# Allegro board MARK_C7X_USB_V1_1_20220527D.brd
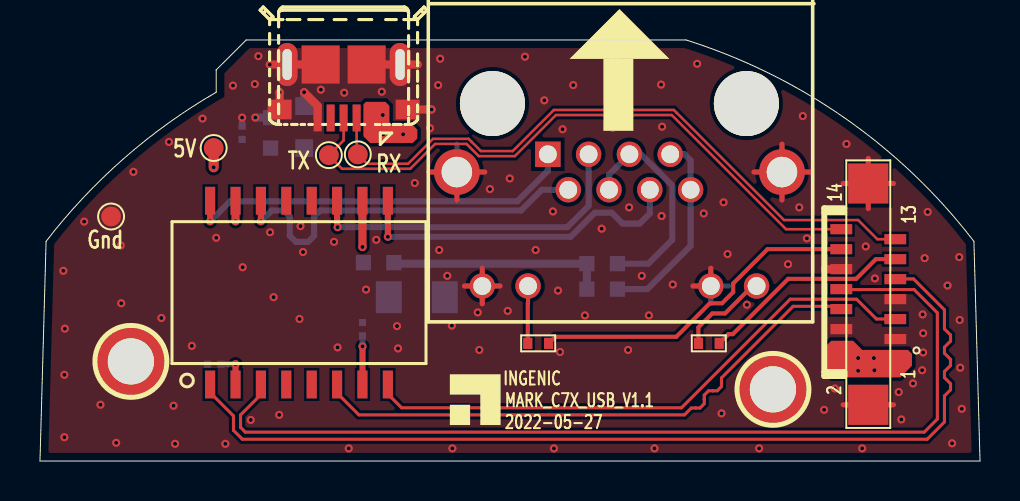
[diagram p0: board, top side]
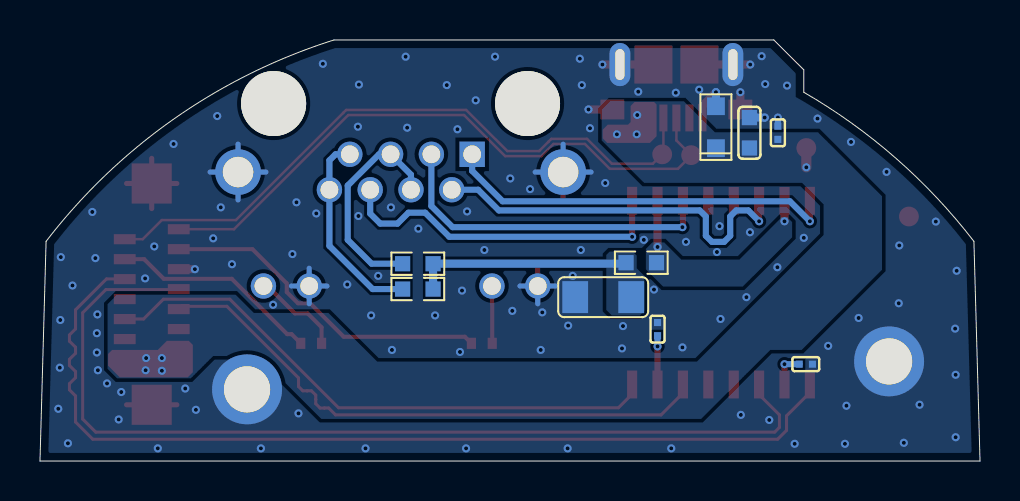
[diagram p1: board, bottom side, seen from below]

Outline 47.02 x 21.08 mm; copper layers: TOP, BOTTOM. Coordinates in mm from the lower left corner of the outline.
Outline path: circle c4.55,4.99 r1.09 ; circle c36.66,3.59 r1.11 ; 0,0 0.3,11 arc(4.19,15.15) 8.81,18.47 8.81,19.58 10.31,21.08 32.31,21.08 arc(40.29,17.15) 46.71,11 47.02,0 0,0

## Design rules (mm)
net group PHY_RX: nets RXN RXP
net group PHY_TX: nets TXN TXP
net group RX: nets RX+ RX-
net group TX: nets TX+ TX-

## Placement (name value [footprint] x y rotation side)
C88  100nF-0201  [C0201]  16.13 6.6 90 bottom
C90  100nF-0201  [C0201]  8.71 4.85 180 bottom
C91  1nF/2KV-1206  [C1206]  18.85 8.2 180 bottom
C162  22uF-0603  [C0603]  11.53 16.43 90 bottom
C163  100nF-0201  [C0201]  10.11 16.43 90 bottom
D14  BZT52C5V1S  [SOD323]  13.21 16.71 270 bottom
HOLE1  T POINT R  [H3D5MM_2D2MM]  4.55 4.99 0 top
HOLE2  T POINT R  [H3D5MM_2D2MM]  36.66 3.59 0 top
J16  MICRO USB  [MICROUSB_B_USB0565]  15.19 17.18 270 top
J20  CON14 0.5mm LT  [FPC-CON14-0D5-LT]  41.43 8.36 90 top
J23  RJ45 With Led  [RJ45-LED-1A]  28.98 23.03 180 top
NOREF  -  []  -171.53 -202.11 0 top
NOREF#2  -  []  0 0 0 top
NOREF#3  -  []  21.77 3.07 0 top
NOREF#4  -  []  42.24 159.56 0 top
NOREF#5  -  []  -67.16 140.11 0 top
NOREF#6  -  []  0 0 90 top
R75  75R/1%-0603  [R0603]  16.94 9.93 180 bottom
R187  300R  [R0402]  24.92 5.89 0 top
R188  300R  [R0402]  33.45 5.89 0 top
R189  75R/1%-0603  [R0603]  28.12 9.88 0 bottom
R190  75R/1%-0603  [R0603]  28.12 8.61 0 bottom
TP39  TP  [TEST_SMD]  8.69 15.67 0 top
TP40  TP  [TEST_SMD]  14.45 15.31 0 top
TP41  TP  [TEST_SMD]  15.9 15.35 0 top
TP42  TP  [TEST_SMD]  3.56 12.24 0 top
U9  FC1680C  [QFP16_1D27]  12.95 8.43 90 top

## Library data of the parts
C88 C90 C91 C162 C163 = CAP
D14 = DIODE_WY
HOLE1 HOLE2 = T POINT R
J16 = MICROUSB_0
J20 = FPCCON_7X2
J23 = RJ45_1X1_LED
R75 R187-R190 = RES
TP39-TP42 = TP
U9 = FC1680C

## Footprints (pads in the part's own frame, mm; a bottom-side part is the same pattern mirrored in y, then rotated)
C0201
  rect 0.356x0.356 smd: 1(-0.33,0) 2(0.33,0)
C0603
  rect 0.762x0.762 smd: 1(-0.762,0) 2(0.762,0)
C1206
  rect 1.295x1.6 smd: 1(-1.4,0) 2(1.4,0)
FPC-CON14-0D5-LT
  rect 0.508x1.092 smd: 1(-3.25,-1.35) 2(-2.75,1.35) 3(-2.25,-1.35) 4(-1.75,1.35) 5(-1.25,-1.35) 6(-0.75,1.35) 7(-0.25,-1.35) 8(0.25,1.35) 9(0.75,-1.35) 10(1.25,1.35) 11(1.75,-1.35) 12(2.25,1.35) 13(2.75,-1.35) 14(3.25,1.35)
  rect 2.007x2.007 smd: 15(-5.54,0) 16(5.54,0)
H3D5MM_2D2MM
  round 3.5 hole 2.311: 1(0,0)
MICROUSB_B_USB0565
  rect 1.346x0.406 smd: 1(0,1.3) 2(0,0.65) 3(0,0) 4(0,-0.65) 5(0,-1.3)
  rect 0.991x1.194 smd: 6(-0.425,-3.2) 7(-0.425,3.2)
  oval 2.159x1.041 hole 1.549x0.457: 8(-2.675,2.825) 9(-2.675,-2.825)
  rect 1.905x1.905 smd: 10(-2.675,-1.15) 11(-2.675,1.15)
QFP16_1D27
  rect 1.397x0.508 smd: 1(-4.6,4.445) 2(-4.6,3.175) 3(-4.6,1.905) 4(-4.6,0.635) 5(-4.6,-0.635) 6(-4.6,-1.905) 7(-4.6,-3.175) 8(-4.6,-4.445) 9(4.6,-4.445) 10(4.6,-3.175) 11(4.6,-1.905) 12(4.6,-0.635) 13(4.6,0.635) 14(4.6,1.905) 15(4.6,3.175) 16(4.6,4.445)
R0402
  rect 0.457x0.559 smd: 1(-0.52,0) 2(0.52,0)
R0603
  rect 0.762x0.762 smd: 1(-0.762,0) 2(0.762,0)
RJ45-LED-1A
  round 3.251 hole 3.251 unplated: (-6.35,5.135) (6.35,5.135)
  rect 1.27x1.27 hole 0.889: 1(3.58,7.675)
  round 1.27 hole 0.889: 2(2.56,9.45) 3(1.54,7.675) 4(0.52,9.45) 5(-0.5,7.675) 6(-1.52,9.45) 7(-2.54,7.675) 8(-3.56,9.45) 11(-6.86,14.27) 12(-4.57,14.27) 13(4.57,14.27) 14(6.86,14.27)
  round 2.286 hole 1.524: 9(-8.13,8.565) 10(8.13,8.565)
SOD323
  rect 0.889x0.889 smd: 1(-1.05,0) 2(1.05,0)
TEST_SMD
  round 0.991 smd: 1(0,0)

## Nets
GND: C88.2 C90.2 C91.1 C162.2 C163.2 D14.1 HOLE1.1(TP) HOLE2.1(TP) J16.5(GND1) J16.6(GND2) J16.7(GND3) J16.8(GND4) J16.9(GND5) J16.10(GND6) J16.11(GND7) J20.3 J20.4 J20.7 J20.10 J20.15(S1) J20.16(S2) J23.9(SH1) J23.10(SH2) J23.12(CON_PIN[11]) J23.14(CON_PIN[13]) TP42.1
VCC_5V: C162.1 C163.1 D14.2 J16.1(VBUS) J20.1 J20.2 TP39.1
LED_LINK/ACT: J20.11 R188.2
LED_SPEED: J20.12 R187.2
RX+: J23.3(CON_PIN[2]) U9.11(RX+/TX+)
RX-: J23.6(CON_PIN[5]) U9.9(RX-/TX-)
RXN: J20.5 U9.8(RD-/TD-)
RXP: J20.6 U9.6(RD+/TD+)
TX+: J23.1(CON_PIN[0]) U9.16(TX+/RX+)
TX-: J23.2(CON_PIN[1]) U9.14(TX-/RX-)
TXN: J20.8 U9.3(TD-/RD-)
TXP: J20.9 U9.1(TD+/RD+)
UART1_RXD: J16.2(D-) J20.13 TP41.1
UART1_TXD: J16.3(D+) J20.14 TP40.1
N16349692: R75.2 U9.10(CT3) U9.15(CT4)
N16349716: C90.1 U9.2(CT1)
N16349770: C88.1 U9.7(CT2)
N16349838: C91.2 R75.1 R189.1 R190.1
N16352020: J23.4(CON_PIN[3]) J23.5(CON_PIN[4]) R189.2
N16352037: J23.7(CON_PIN[6]) J23.8(CON_PIN[7]) R190.2
N16360139: J23.11(CON_PIN[10]) R188.1
N16602826: J23.13(CON_PIN[12]) R187.1

Pads without a net: J16 4; U9 4 5 12 13

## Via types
v1: diameter 0.406, hole 0.203, TOP to BOTTOM, 130 vias

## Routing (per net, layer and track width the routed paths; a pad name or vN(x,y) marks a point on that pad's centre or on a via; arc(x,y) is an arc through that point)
GND: length 50.1
  TOP w0.254: J20.16 41.43,15.15 ; J20.16 40.17,13.9 ; J20.16 42.68,13.9 ; J20.16 41.43,12.64 ; J23.9 38.51,14.47 ; J23.9 37.11,13.07 ; J23.9 35.71,14.47 ; J23.9 37.11,15.86 ; 21.23,8.76 J23.14 ; J23.14 22.12,7.87 ; J23.14 22.12,9.65 ; J23.14 23.01,8.76 ; 19.45,14.47 J23.10 ; J23.10 20.85,13.07 ; J23.10 22.25,14.47 ; 32.66,8.76 J23.12 33.55,9.65 ; 42.68,2.82 J20.15 40.17,2.82
  TOP w0.406: v1(13.21,18.47) 13.89,17.79 J16.5 ; J16.7 v1(19.58,17.6) ; J20.10 v1(39.27,9.61) ; v1(11.49,19.85) J16.9 J16.10 ; J16.11 J16.8 v1(18.88,19.85) ; J16.6 v1(11.99,18.47)
  BOTTOM w0.254: 35.71,14.47 J23.9 ; J23.9 37.11,15.86 ; J23.9 37.11,13.07 ; J23.9 38.51,14.47 ; J23.14 23.01,8.76 ; J23.14 22.12,7.87 ; J23.14 21.23,8.76 ; J23.10 22.25,14.47 ; J23.10 19.45,14.47 ; J23.10 20.85,15.86 ; J23.12 34.44,8.76 ; J23.12 33.55,9.65 ; J23.12 33.55,7.87 ; J23.12 32.66,8.76
  BOTTOM w0.305: C163.2 v1(10.11,17.2)
  BOTTOM w0.406: D14.1 v1(13.21,18.47) ; C162.2 v1(10.77,17.2)
  vias: v1(1.17,9.53) v1(1.24,6.63) v1(1.22,4.32) v1(1.22,1.19) v1(2.21,11.99) v1(3.02,2.82) v1(3.81,0.91) v1(4.04,10.79) v1(4.06,7.9) v1(4.67,14.48) v1(6.07,7.16) v1(6.45,15.98) v1(6.68,2.77) v1(6.76,0.86) v1(7.59,5.77) v1(8.13,17.14) v1(8.81,11.18) v1(9.27,0.86) v1(9.65,18.8) v1(10.13,9.7) v1(10.54,2.06) v1(10.74,18.87) v1(10.92,20.27) v1(11.51,11.46) v1(11.68,8.2) v1(11.96,2.31) v1(13.03,11.76) v1(12.98,7.11) v1(13.16,10.46) v1(14.05,18.59) v1(14.71,10.97) v1(14.88,5.69) v1(15.21,18.44) v1(15.44,0.64) v1(16.31,8.59) v1(16.81,11.07) v1(17.09,18.49) v1(17.86,6.76) v1(17.91,5.64) v1(18.75,13.92) v1(19.51,16.66) v1(19.91,18.82) v1(20.02,20.14) v1(19.96,10.57) v1(20.37,9.27) v1(20.6,6.78) v1(20.62,0.64) v1(21.89,7.44) v1(21.97,5.56) v1(22.5,13.61) v1(23.39,7.52) v1(23.5,14.15) v1(24.26,20.24) v1(24.79,10.57) v1(25.22,18.06) v1(25.65,12.5) v1(25.7,0.64) v1(25.91,8.53) v1(26.01,5.46) v1(26.14,16.61) v1(26.67,18.82) v1(27.25,7.29) v1(28.09,11.63) v1(28.73,20.24) v1(28.65,16.69) v1(29.41,5.56) v1(29.46,12.7) v1(30.1,9.27) v1(30.45,7.29) v1(30.73,0.64) v1(31.06,18.85) v1(31.11,16.74) v1(31.09,12.27) v1(31.65,8.84) v1(32.87,19.89) v1(33.2,12.4) v1(34.09,2.39) v1(34.19,12.95) v1(34.39,10.36) v1(35.36,7.82) v1(35.97,0.64) v1(37.41,9.86) v1(37.97,12.7) v1(38.15,17.27) v1(38.35,11.15) v1(39.22,2.57) v1(39.75,3.63) v1(40.34,15.88) v1(41.12,0.64) v1(41.3,10.74) v1(41.76,9.14) v1(42.95,3.45) v1(43.08,2.08) v1(43.66,3.89) v1(44.15,7.34) v1(44.12,4.55) v1(44.25,10.16) v1(44.17,6.4) v1(44.17,5.44) v1(44.4,12.47) v1(45.39,8.79) v1(45.62,0.89) v1(45.97,10.21) v1(46,7.06) v1(46.02,4.67) v1(46.1,2.62)
VCC_5V: length 1
  TOP w0.508: TP39.1 v1(8.69,14.71)
  vias: v1(17.14,17.32) v1(17.17,16.36) v1(18.16,16.36) v1(40.92,5.16) v1(40.92,4.52) v1(41.71,5.16) v1(41.73,4.55)
LED_LINK/ACT: length 10.6
  TOP w0.203: J20.11 41.81,10.11 40.82,9.12 37.42,9.12 34.65,6.35 34.43,6.35 R188.2
LED_SPEED: length 16.8
  TOP w0.203: J20.12 36.39,10.61 34.67,8.89 34.67,8.46 34.11,7.9 33.5,7.9 31.83,6.22 25.77,6.22 R187.2
RX+: length 16.9
  TOP w0.305: v1(14.88,11.71) 14.86,11.73 U9.11
  BOTTOM w0.305: J23.3 27.44,12.77 26.38,11.71 v1(14.88,11.71)
RX-: length 17
  TOP w0.305: U9.9 v1(17.4,11.23)
  BOTTOM w0.305: v1(17.4,11.23) 26.54,11.23 27.75,12.43 28.59,12.43 29.13,11.89 30,11.89 30.5,12.39 J23.6
RXN: length 28.8
  TOP w0.152: J20.5 42.77,7.11 41.83,7.11 40.84,8.1 37.52,8.1 32.09,2.67 18.08,2.67 17.4,3.35 U9.8
RXP: length 28.9
  TOP w0.152: J20.6 39.94,7.75 37.67,7.75 34.08,4.16 34.08,3.95 34.09,3.95 34.09,3.73 33.87,3.52 33.65,3.52 33.44,3.52 33.22,3.3 33.22,3.09 33.22,2.87 33.01,2.65 32.79,2.65 32.58,2.65 32.23,2.31 15.95,2.31 14.86,3.4 U9.6
TX+: length 19.8
  TOP w0.305: U9.16 v1(8.51,12)
  BOTTOM w0.305: v1(8.51,12) 9.51,13 23.88,13 25.4,14.53 J23.1
TX-: length 19.5
  TOP w0.305: 11.05,13.03 v1(11.05,12)
  BOTTOM w0.305: J23.2 25.1,13.58 24.07,12.55 14.02,12.55 13.71,12.24 13.71,11.28 13.41,10.97 12.8,10.97 12.49,11.28 12.49,12.24 12.19,12.55 11.59,12.55 v1(11.05,12)
TXN: length 48.4
  TOP w0.152: J20.8 40.1,8.59 43.72,8.59 44.88,7.42 44.88,2.1 44.23,1.45 10.27,1.45 10.03,1.68 10.03,2.31 11.05,3.33 11.05,3.83
TXP: length 48.4
  TOP w0.152: U9.1 8.51,3.43 9.68,2.26 9.68,1.54 10.12,1.09 44.37,1.09 45.24,1.96 45.24,3.26 45.54,3.57 45.54,3.87 45.24,4.18 45.24,4.48 45.54,4.79 45.54,5.09 45.24,5.4 45.24,5.7 45.54,6 45.54,6.31 45.24,6.61 45.24,7.57 43.69,9.12 42.79,9.12 J20.9
UART1_RXD: length 33.2
  TOP w0.127: J20.13 41.88,11.11 40.92,12.06 37.21,12.06 31.7,17.58 25.7,17.58 23.64,15.52 22.05,15.52 21.44,16.13 19.66,16.13 18.41,14.88 16.37,14.88 TP41.1 15.84,15.42 J16.2
UART1_TXD: length 32.1
  TOP w0.127: J20.14 37.31,11.61 31.6,17.32 25.81,17.32 23.75,15.27 21.95,15.27 21.34,15.88 19.76,15.88 18.52,14.63 15.11,14.63 14.45,15.29 TP40.1 15.19,16.05 J16.3
N16349692: length 3.3
  TOP w0.406: U9.10 v1(16.13,10.72) ; v1(9.78,12) U9.15
N16349716: length 1.8
  TOP w0.305: U9.2 v1(9.78,4.85)
  BOTTOM w0.305: C90.1 v1(9.78,4.85)
N16349770: length 2.4
  TOP w0.305: U9.7 v1(16.13,5.74)
  BOTTOM w0.305: v1(16.13,5.74) C88.1
N16349838: length 10.9
  BOTTOM w0.406: R75.1 17.75,9.88 R189.1 R190.1
N16352020: length 10.9
  BOTTOM w0.305: R189.2 30.43,9.88 31.62,11.07 31.62,13.79 30.06,15.36 J23.5 28.46,14.34 J23.4
N16352037: length 10
  BOTTOM w0.305: R190.2 30.38,8.61 32.54,10.77 J23.8 32.54,15.05 32.24,15.36 J23.7
N16360139: length 4.6
  TOP w0.203: R188.1 32.93,6.69 33.63,7.39 34.26,7.39 35.64,8.76 J23.11
N16602826: length 2.9
  TOP w0.203: J23.13 24.41,7.9 24.4,7.89 R187.1

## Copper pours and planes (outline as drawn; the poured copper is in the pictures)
GND on TOP: 0.42,0.41 0.71,10.85 4.51,14.89 9.02,18.11 9.22,18.23 9.22,19.41 10.48,20.68 32.25,20.68 40.02,16.84 46.31,10.85 46.6,0.41
GND on BOTTOM: 0.42,0.41 0.71,10.85 4.51,14.89 9.02,18.11 9.22,18.23 9.22,19.41 10.48,20.68 32.25,20.68 40.02,16.84 46.31,10.85 46.6,0.41 ; 1 cut-out
VCC_5V on TOP (solid shape): 41.12,5.56 43.41,5.56 43.61,5.36 43.61,4.78 43.03,4.19 39.62,4.19 39.37,4.45 39.37,5.82 39.57,6.02 40.67,6.02
VCC_5V on TOP (solid shape): 17.48,17.78 17.48,16.97 17.6,16.84 18.62,16.84 18.87,16.59 18.87,16.15 18.64,15.93 16.51,15.93 16.18,16.26 16.18,17.86 16.31,17.98 17.27,17.98
VCC_5V on BOTTOM: 4.9,9.58 4.9,13.26 8.1,16.46 13.26,16.46 14.81,18.01 18.49,18.01 18.92,17.58 18.92,16.05 16.8,13.93 8.9,13.93 7.82,12.85 7.82,11.32 14.16,4.98 30.15,4.98 32.59,7.42 36.32,7.42 37.24,8.33 43.15,8.33 43.64,7.85 43.64,4.62 43.15,4.14 39.47,4.14 38.35,5.26 36.09,5.26 32.94,2.11 13.94,2.11 10.49,5.56 8.92,5.56
N16349692 on BOTTOM: 9.88,12.24 9.68,12.24 9.4,11.96 9.4,11.2 11.86,8.74 15.85,8.74 16.71,9.6 16.71,10.62 16.38,10.95 15.8,10.95 14.94,10.08 12.04,10.08
N16349838 on BOTTOM: 18.52,10.49 17.37,10.49 17.17,10.29 17.17,9.65 16.79,9.27 16.79,7.52 17.02,7.29 18.41,7.29 18.69,7.57 18.69,10.31

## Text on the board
Ref Des/Silkscreen Top: Gnd | 5V | TX | RX
DIMENSION: XX_XX_XXXXX | XX | XXXXX | XXXX-XX-XX
User.6: FIGURE | SIZE | 8.0 | 35.0 | 60.0 | 90.98 | 128.0 | 61.0x18.0 | DRILL CHART: TOP to BOTTOM | ALL UNITS ARE IN MILS | PLATED | NON-PLATED | QTY | 130 | 11 | 1 | 2
